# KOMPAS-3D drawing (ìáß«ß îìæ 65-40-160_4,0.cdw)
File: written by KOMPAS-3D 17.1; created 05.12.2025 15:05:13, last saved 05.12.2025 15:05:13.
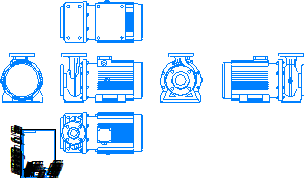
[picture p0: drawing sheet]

Sheet 1: A4, portrait

Title block, sheet 1: name: Насос МНС / 65-40-160_4,0; material: Сталь 10  ГОСТ 1050-88; mass: 129,66; sheets: 1; sheet format: A4

Views: Проекционный вид 2, Проекционный вид 3, Проекционный вид 4, Проекционный вид 5, Проекционный вид 6
Referenced files in \\adlc.lan\data\АДЛ_ПКД\3D-модели\ADL production\Насосы ГРАНПАМП\Насосы ГРАНПАМП серии МНС\KOMPAS 3D\: Насос МНС 65-40-160_4,0.m3d
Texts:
  Andrey
  АДЛ
Dimensions and other numbers on the sheet: 1:1; 1; 65-40-160_4,0; 129,66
